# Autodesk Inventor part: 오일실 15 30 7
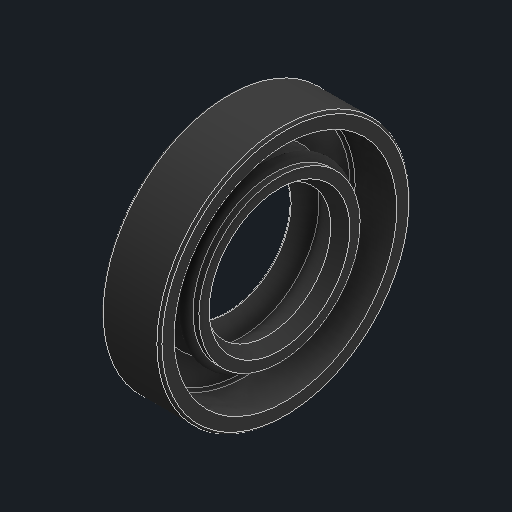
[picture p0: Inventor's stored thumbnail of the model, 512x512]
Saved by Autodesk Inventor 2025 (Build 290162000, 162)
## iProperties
Created: 2025-08
Part Number: 오일실 15 30 7
Material: 고무
Description: 오일-실
Document SubType Name: Modeling
Designer: infra11
Density: 0.93 g/cm^3
Appearance: 기본값
Author: jhkim
Sending System: Autodesk Inventor 2026
Preprocessor: ST-DEVELOPER v20.1
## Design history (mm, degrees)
feature "Solid1"
node "솔리드1"
